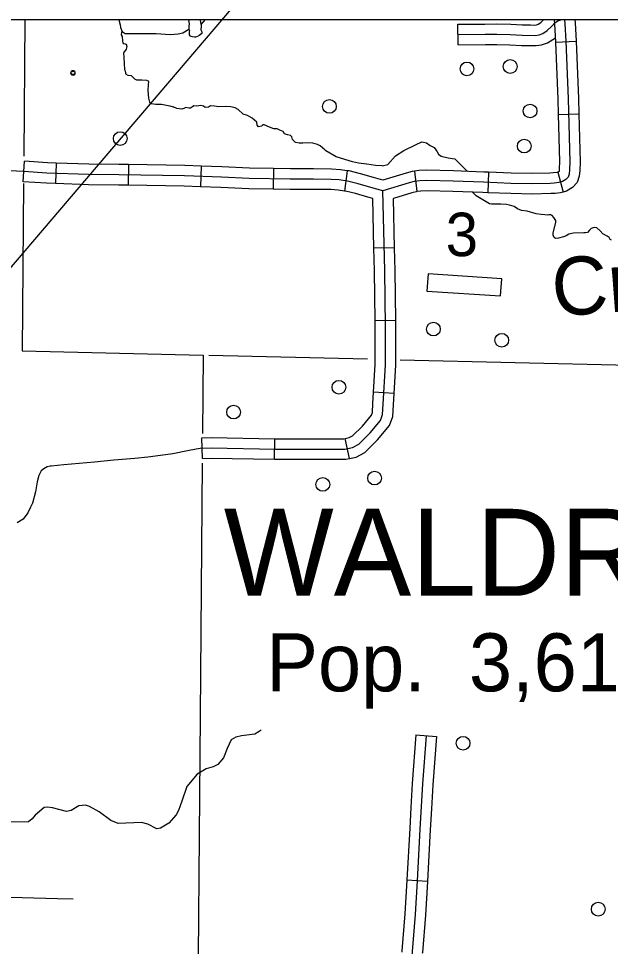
# Model space of a CAD drawing. Extents: x 1382482 to 1385815, y 1168351 to 1170484.
# Drawn here: x 1384491.5 to 1384663.8, y 1169309.6 to 1169580 of the extents above; entities that cross this region are included whole.
import ezdxf

# ---------------------------------------------------------------- set-up
doc = ezdxf.new("R2010")
doc.units = 0
for name, color, linetype in [('32', 7, 'Continuous'), ('35', 7, 'Continuous'), ('45', 7, 'Continuous'), ('5', 7, 'Continuous'), ('57', 7, 'Continuous'), ('6', 7, 'Continuous'), ('Default', 7, 'Continuous'), ('R_Dimension', 7, 'Continuous'), ('R_No Plot', 7, 'Continuous')]:
    doc.layers.add(name, color=color, linetype=linetype)

msp = doc.modelspace()

# ---------------------------------------------------------------- linework, layer by layer
at = {"layer": '32'}
for p, q in [((1384647.84, 1169573.11), (1384653.84, 1169573.35)), ((1384648.63, 1169552.04), (1384654.63, 1169552.21)), ((1384502.45, 1169537.87), (1384502.23, 1169531.87)), ((1384523.5, 1169537.4), (1384523.41, 1169531.4)), ((1384544.67, 1169536.98), (1384544.46, 1169530.98)), ((1384565.73, 1169536.27), (1384565.62, 1169530.27)), ((1384587.19, 1169535.63), (1384586.34, 1169529.69)), ((1384606.78, 1169535.5), (1384607.45, 1169529.54)), ((1384628.32, 1169535.19), (1384628.1, 1169529.2)), ((1384648.52, 1169535.22), (1384650.07, 1169529.42)), ((1384600.95, 1169513.17), (1384594.95, 1169513.04)), ((1384601.3, 1169492.03), (1384595.3, 1169491.94)), ((1384600.82, 1169470.7), (1384594.83, 1169471.07)), ((1384545.05, 1169451.79), (1384544.88, 1169457.79)), ((1384566.03, 1169451.56), (1384566.13, 1169457.56)), ((1384587.79, 1169451.76), (1384586.58, 1169457.63))]:
    msp.add_line(p, q, dxfattribs=at)
for points in [[(1384650.48, 1169579.7), (1384650.58, 1169578.46), (1384650.84, 1169573.36), (1384651.51, 1169556.59), (1384652.03, 1169538.25), (1384651.92, 1169535.94), (1384651.8, 1169534.67), (1384651.47, 1169533.74), (1384650.87, 1169533.07), (1384649.87, 1169532.47), (1384648.75, 1169532.17), (1384647.45, 1169532.02), (1384646.29, 1169531.95), (1384641.15, 1169531.8), (1384634.86, 1169531.95), (1384626.81, 1169532.25), (1384618.03, 1169532.62), (1384610.35, 1169532.81), (1384608.33, 1169532.66), (1384606.7, 1169532.47), (1384605.17, 1169532.06), (1384597.57, 1169529.79)], [(1384647.48, 1169579.7), (1384647.58, 1169578.28), (1384647.84, 1169573.22), (1384647.84, 1169573.11)], [(1384653.49, 1169579.7), (1384653.57, 1169578.65), (1384653.83, 1169573.49), (1384653.84, 1169573.35)], [(1384647.84, 1169573.11), (1384648.51, 1169556.48), (1384648.63, 1169552.04)], [(1384653.84, 1169573.35), (1384654.5, 1169556.69), (1384654.63, 1169552.21)], [(1384648.63, 1169552.04), (1384649.03, 1169538.28), (1384648.92, 1169536.14), (1384648.85, 1169535.36), (1384648.69, 1169535.26), (1384648.52, 1169535.22)], [(1384654.63, 1169552.21), (1384655.03, 1169538.22), (1384654.91, 1169535.73), (1384654.76, 1169534.02), (1384654.1, 1169532.18), (1384652.8, 1169530.73), (1384651.04, 1169529.68), (1384650.07, 1169529.42)], [(1384502.23, 1169531.87), (1384499.56, 1169531.97), (1384492.77, 1169532.42), (1384493.17, 1169538.41)], [(1384502.45, 1169537.87), (1384499.87, 1169537.96), (1384493.17, 1169538.41)], [(1384523.5, 1169537.4), (1384520.68, 1169537.44), (1384511.93, 1169537.52), (1384502.45, 1169537.87)], [(1384597.57, 1169529.79), (1384594.03, 1169530.77), (1384590.31, 1169531.85), (1384587.22, 1169532.6), (1384584.87, 1169532.93), (1384582.49, 1169533.12), (1384577.35, 1169533.16), (1384570.59, 1169533.18), (1384558.6, 1169533.4), (1384550.52, 1169533.77), (1384539.79, 1169534.15), (1384520.65, 1169534.44), (1384511.86, 1169534.52), (1384499.72, 1169534.96), (1384492.97, 1169535.41)], [(1384544.67, 1169536.98), (1384539.87, 1169537.14), (1384523.5, 1169537.4)], [(1384565.73, 1169536.27), (1384558.69, 1169536.4), (1384550.64, 1169536.77), (1384544.67, 1169536.98)], [(1384587.19, 1169535.63), (1384585.2, 1169535.92), (1384582.62, 1169536.12), (1384577.36, 1169536.16), (1384570.62, 1169536.18), (1384565.73, 1169536.27)], [(1384606.78, 1169535.5), (1384606.13, 1169535.43), (1384604.35, 1169534.95), (1384597.54, 1169532.91), (1384594.85, 1169533.66), (1384591.08, 1169534.75), (1384587.78, 1169535.55), (1384587.19, 1169535.63)], [(1384628.32, 1169535.19), (1384626.93, 1169535.25), (1384618.13, 1169535.62), (1384610.27, 1169535.81), (1384608.05, 1169535.65), (1384606.78, 1169535.5)], [(1384648.52, 1169535.22), (1384648.19, 1169535.13), (1384647.18, 1169535.01), (1384646.15, 1169534.95), (1384641.14, 1169534.8), (1384634.95, 1169534.95), (1384628.32, 1169535.19)], [(1384523.41, 1169531.4), (1384520.61, 1169531.44), (1384511.79, 1169531.52), (1384502.23, 1169531.87)], [(1384544.46, 1169530.98), (1384539.72, 1169531.15), (1384523.41, 1169531.4)], [(1384565.62, 1169530.27), (1384558.5, 1169530.4), (1384550.4, 1169530.78), (1384544.46, 1169530.98)], [(1384544.96, 1169454.79), (1384547.55, 1169454.87), (1384566.26, 1169454.55), (1384584.01, 1169454.55), (1384586.5, 1169454.55), (1384588.75, 1169455.02), (1384590.54, 1169455.95), (1384593.81, 1169459.22), (1384596.85, 1169462.88), (1384597.47, 1169464.6), (1384597.63, 1169467.63), (1384598.33, 1169479.08), (1384598.33, 1169490.17), (1384598.09, 1169506.52), (1384597.57, 1169529.79)], [(1384586.34, 1169529.69), (1384584.54, 1169529.95), (1384582.36, 1169530.12), (1384577.33, 1169530.16), (1384570.56, 1169530.18), (1384565.62, 1169530.27)], [(1384594.62, 1169527.5), (1384593.21, 1169527.89), (1384589.54, 1169528.95), (1384586.65, 1169529.65), (1384586.34, 1169529.69)], [(1384628.1, 1169529.2), (1384626.7, 1169529.25), (1384617.93, 1169529.62), (1384610.42, 1169529.8), (1384608.61, 1169529.67), (1384607.45, 1169529.54)], [(1384594.95, 1169513.04), (1384594.62, 1169527.5)], [(1384607.45, 1169529.54), (1384607.26, 1169529.52), (1384605.99, 1169529.18), (1384600.62, 1169527.57)], [(1384600.95, 1169513.17), (1384600.62, 1169527.57)], [(1384650.07, 1169529.42), (1384649.31, 1169529.22), (1384647.71, 1169529.04), (1384646.43, 1169528.95), (1384641.16, 1169528.8), (1384634.77, 1169528.95), (1384628.1, 1169529.2)], [(1384595.3, 1169491.94), (1384595.09, 1169506.47), (1384594.95, 1169513.04)], [(1384601.3, 1169492.03), (1384601.09, 1169506.58), (1384600.95, 1169513.17)], [(1384594.83, 1169471.07), (1384595.33, 1169479.17), (1384595.33, 1169490.15), (1384595.3, 1169491.94)], [(1384600.82, 1169470.7), (1384601.33, 1169478.99), (1384601.33, 1169490.19), (1384601.3, 1169492.03)], [(1384586.58, 1169457.63), (1384587.74, 1169457.87), (1384588.75, 1169458.4), (1384591.59, 1169461.25), (1384594.21, 1169464.4), (1384594.5, 1169465.2), (1384594.63, 1169467.8), (1384594.83, 1169471.07)], [(1384587.79, 1169451.76), (1384589.77, 1169452.17), (1384592.34, 1169453.51), (1384596.03, 1169457.2), (1384599.49, 1169461.37), (1384600.44, 1169463.99), (1384600.62, 1169467.46), (1384600.82, 1169470.7)], [(1384544.88, 1169457.79), (1384547.54, 1169457.87), (1384566.13, 1169457.56)], [(1384566.13, 1169457.56), (1384566.29, 1169457.55), (1384584.01, 1169457.55), (1384586.19, 1169457.55), (1384586.58, 1169457.63)], [(1384545.05, 1169451.79), (1384547.57, 1169451.86), (1384566.03, 1169451.56)], [(1384566.03, 1169451.56), (1384566.24, 1169451.55), (1384584.01, 1169451.55), (1384586.8, 1169451.55), (1384587.79, 1169451.76)]]:
    msp.add_lwpolyline(points, dxfattribs=at)
at = {"layer": '35'}
for points in [[(1384520.68, 1169579.7), (1384520.77, 1169579.22), (1384521.05, 1169578.09), (1384521.14, 1169577.38), (1384521.65, 1169576.22), (1384522.48, 1169575.64), (1384523.26, 1169575.57), (1384524.15, 1169575.57), (1384525.24, 1169575.57), (1384527.46, 1169575.61), (1384529.94, 1169575.57), (1384531.58, 1169575.57), (1384535.63, 1169575.33), (1384537.92, 1169575.48), (1384539.32, 1169575.84), (1384541.02, 1169576.88)], [(1384541.22, 1169579.7), (1384540.98, 1169579.14), (1384541, 1169578.97), (1384541.16, 1169578.5), (1384541.08, 1169577.68), (1384541.02, 1169576.88), (1384541.16, 1169576.67), (1384541.27, 1169576.53), (1384541.16, 1169576.07), (1384541.19, 1169575.23), (1384541.35, 1169574.92), (1384541.6, 1169574.84), (1384542.13, 1169574.72), (1384542.67, 1169574.68), (1384543.08, 1169574.68), (1384543.39, 1169574.76), (1384543.84, 1169574.96)], [(1384544.21, 1169579.7), (1384544.35, 1169579.48), (1384544.48, 1169578.83), (1384544.53, 1169578.31), (1384544.64, 1169578.2), (1384544.68, 1169577.79)], [(1384544.64, 1169578.2), (1384545.93, 1169579.7)], [(1384521.65, 1169576.22), (1384521.4, 1169576.02), (1384521.36, 1169575.24), (1384521.59, 1169574.69), (1384521.75, 1169573.37), (1384521.79, 1169572.94), (1384521.9, 1169572.71), (1384522.52, 1169572.59), (1384522.8, 1169572.51), (1384523.03, 1169571.85), (1384522.76, 1169571), (1384522.06, 1169569.98), (1384522.1, 1169568.62), (1384522.29, 1169565.16), (1384522.49, 1169564.77), (1384522.6, 1169564.07), (1384522.64, 1169563.83), (1384523.26, 1169563.48), (1384524.24, 1169563.41), (1384525.21, 1169562.43), (1384525.83, 1169562.12), (1384526.46, 1169562.08), (1384527.39, 1169562.12), (1384528.75, 1169562), (1384529.22, 1169561.85), (1384529.3, 1169561.54), (1384529.18, 1169560.72), (1384529.06, 1169559.05), (1384529.26, 1169556.75), (1384529.61, 1169555.58), (1384530.11, 1169555.19), (1384531.44, 1169555.04), (1384533.11, 1169555.04), (1384535.48, 1169554.57), (1384536.48, 1169554.24)], [(1384544.68, 1169577.79), (1384544.57, 1169576.69), (1384544.79, 1169576.14), (1384544.79, 1169575.95), (1384544.79, 1169575.62), (1384544.02, 1169575), (1384543.84, 1169574.96)], [(1384580.64, 1169541.67), (1384579.29, 1169542.89), (1384578.51, 1169543.28), (1384577.11, 1169543.67), (1384575.86, 1169543.75), (1384574.23, 1169543.67), (1384573.14, 1169543.67), (1384572.13, 1169543.9), (1384571.27, 1169544.76), (1384571.04, 1169545.46), (1384570.65, 1169545.85), (1384569.79, 1169546.08), (1384568.93, 1169546.39), (1384568.47, 1169547.09), (1384567.53, 1169547.41), (1384566.76, 1169547.8), (1384565.82, 1169547.8), (1384564.5, 1169548.34), (1384563.02, 1169548.96), (1384562.63, 1169548.96), (1384562.16, 1169548.65), (1384561.38, 1169548.42), (1384560.92, 1169548.89), (1384560.84, 1169549.82), (1384559.52, 1169550.91), (1384558.12, 1169551.69), (1384556.9, 1169552.14), (1384555.46, 1169553.42), (1384554.56, 1169553.93), (1384553.32, 1169554.24), (1384551.64, 1169554.32), (1384549.7, 1169554.24), (1384548.53, 1169554.47), (1384547.33, 1169554.51), (1384546.75, 1169554.12), (1384545.85, 1169554.08), (1384545.34, 1169554.47), (1384544.53, 1169554.59), (1384543.4, 1169554.47), (1384542.51, 1169554.51), (1384542.12, 1169554.2), (1384541.57, 1169553.81), (1384541.07, 1169553.81), (1384540.21, 1169554.08), (1384539.63, 1169553.73), (1384539.04, 1169553.58), (1384538.27, 1169553.65), (1384537.53, 1169553.77), (1384536.48, 1169554.24)], [(1384597.39, 1169537.02), (1384598.98, 1169537.42), (1384601.25, 1169539.94), (1384603.66, 1169541.53), (1384607.05, 1169543.21), (1384608.91, 1169544.03), (1384609.42, 1169543.95), (1384610.28, 1169543.75), (1384611.29, 1169542.94), (1384612.46, 1169542.35), (1384613, 1169541.69), (1384613.35, 1169541.11), (1384613.78, 1169540.41), (1384614.56, 1169539.86), (1384616.55, 1169539.36), (1384618.53, 1169539.09), (1384619.84, 1169537.71), (1384622.23, 1169535.44)], [(1384597.39, 1169537.02), (1384595.43, 1169537.15), (1384592.93, 1169537.52), (1384590.44, 1169537.81), (1384588.66, 1169538.21), (1384583.93, 1169539.65), (1384580.92, 1169541.46), (1384580.64, 1169541.67)], [(1384647.89, 1169520.62), (1384647.92, 1169521.13), (1384647.53, 1169521.67), (1384647.3, 1169522.03), (1384646.83, 1169522.63), (1384646.49, 1169522.74), (1384645.85, 1169522.74), (1384645.46, 1169522.68), (1384644.69, 1169522.74), (1384643.63, 1169522.86), (1384642.18, 1169523.09), (1384639.62, 1169523.88), (1384637.97, 1169524.05), (1384636.76, 1169524.56), (1384635.74, 1169525.2), (1384634.39, 1169525.55), (1384633.51, 1169525.83), (1384631.92, 1169525.86), (1384630.42, 1169525.93), (1384629.17, 1169525.89), (1384628.63, 1169526.02), (1384627.63, 1169526.56), (1384627.14, 1169526.86), (1384624.72, 1169528.36), (1384623.66, 1169529.38)], [(1384647.12, 1169517.48), (1384647.89, 1169520.62)], [(1384664.17, 1169515.41), (1384663.78, 1169515.62), (1384663.48, 1169516.14), (1384662.84, 1169516.61), (1384661.64, 1169517.21), (1384660.87, 1169518.11), (1384659.89, 1169518.96), (1384659.29, 1169519.09), (1384658.82, 1169519.01), (1384658.22, 1169518.79), (1384657.74, 1169518.28), (1384657.1, 1169517.68), (1384656.59, 1169517.55), (1384656.07, 1169517.55), (1384653.03, 1169517.42), (1384651.71, 1169517.16), (1384650.89, 1169516.65), (1384650.16, 1169516.35), (1384648.71, 1169516.01), (1384647.81, 1169515.92), (1384647.42, 1169516.18), (1384647.12, 1169516.82), (1384647.12, 1169517.46), (1384647.12, 1169517.48)], [(1384562.12, 1169372.68), (1384561.57, 1169372.26), (1384560.22, 1169371.5), (1384556.4, 1169370.99), (1384554.69, 1169370.58), (1384553.38, 1169369.81), (1384552.24, 1169367.32), (1384551.14, 1169364.63), (1384549.52, 1169362.66), (1384548.16, 1169361.93), (1384546.14, 1169361.36), (1384543.51, 1169359.86), (1384540.47, 1169356.2), (1384538.98, 1169351.99), (1384538, 1169349.19), (1384537.33, 1169347.98), (1384535.27, 1169345.57), (1384532.81, 1169344.07), (1384531.7, 1169343.91), (1384529.06, 1169345.29), (1384527.3, 1169345.72), (1384520.45, 1169345.43), (1384518.33, 1169346.29), (1384514.92, 1169348.87), (1384512.08, 1169350.45), (1384510.92, 1169350.8), (1384509.05, 1169350.58), (1384506.75, 1169349.25), (1384505.43, 1169348.96), (1384501.36, 1169350.01), (1384499.93, 1169350.2), (1384498.89, 1169350.07), (1384496.31, 1169347.9), (1384495.44, 1169346.85), (1384494.37, 1169345.96), (1384488.05, 1169345.82)]]:
    msp.add_lwpolyline(points, dxfattribs=at)
at = {"layer": '45'}
for p, q in [((1384619.47, 1169572.3), (1384619.42, 1169578.3)), ((1384607.15, 1169371.24), (1384613.13, 1169370.8)), ((1384604.53, 1169329.03), (1384610.52, 1169328.69))]:
    msp.add_line(p, q, dxfattribs=at)
for points in [[(1384619.42, 1169578.3), (1384627.29, 1169578.37), (1384630.75, 1169578.45), (1384634.78, 1169578.29), (1384638.16, 1169578.11), (1384640.58, 1169578.09)], [(1384619.44, 1169575.3), (1384627.34, 1169575.37), (1384630.73, 1169575.44), (1384634.64, 1169575.3), (1384638.07, 1169575.11), (1384641.98, 1169575.07), (1384643.02, 1169575.22), (1384644.14, 1169575.63), (1384645.44, 1169576.45), (1384646.71, 1169577.72), (1384647.7, 1169578.8), (1384648.48, 1169579.28), (1384649.12, 1169579.51), (1384649.79, 1169579.65)], [(1384640.58, 1169578.09), (1384641.78, 1169578.07), (1384642.28, 1169578.15), (1384642.81, 1169578.34), (1384643.56, 1169578.81), (1384644.44, 1169579.7)], [(1384640.53, 1169572.09), (1384642.18, 1169572.07), (1384643.76, 1169572.3), (1384645.47, 1169572.92), (1384647.78, 1169574.38)], [(1384619.47, 1169572.3), (1384627.39, 1169572.37), (1384630.71, 1169572.44), (1384634.5, 1169572.3), (1384637.97, 1169572.11), (1384640.53, 1169572.09)], [(1384610.14, 1169371.02), (1384609.13, 1169356.96), (1384608.36, 1169343.82), (1384607.52, 1169328.74), (1384606.92, 1169318.92), (1384606.08, 1169308.13), (1384605.63, 1169302.01), (1384605.42, 1169299.98), (1384605.17, 1169298.24), (1384604.62, 1169296.5), (1384603.9, 1169294.76), (1384603.43, 1169293.49), (1384602.88, 1169292.35), (1384602.75, 1169291.55), (1384603.13, 1169290.66), (1384603.51, 1169289.94), (1384603.86, 1169289.02)], [(1384607.15, 1169371.24), (1384606.13, 1169357.15), (1384605.72, 1169350.12)], [(1384613.13, 1169370.8), (1384612.12, 1169356.76), (1384611.71, 1169349.77)], [(1384605.72, 1169350.12), (1384605.37, 1169343.99), (1384604.53, 1169329.03)], [(1384611.71, 1169349.77), (1384611.36, 1169343.65), (1384610.52, 1169328.69)], [(1384604.53, 1169329.03), (1384604.52, 1169328.92), (1384603.93, 1169319.12), (1384603.09, 1169308.36), (1384603.06, 1169308.01)], [(1384610.52, 1169328.69), (1384610.51, 1169328.57), (1384609.92, 1169318.71), (1384609.07, 1169307.9), (1384609.04, 1169307.58)]]:
    msp.add_lwpolyline(points, dxfattribs=at)
at = {"layer": '5'}
for points in [[(1384493.32, 1169579.7), (1384493, 1169539.9)], [(1384546.86, 1169481.89), (1384593.12, 1169480.79)], [(1384602.62, 1169480.56), (1384703.1, 1169478.17)]]:
    msp.add_lwpolyline(points, dxfattribs=at)
at = {"layer": '57'}
for p, q in [((1384610.7, 1169505.57), (1384610.37, 1169500.58)), ((1384632.15, 1169504.15), (1384610.7, 1169505.57)), ((1384631.82, 1169499.16), (1384632.15, 1169504.15)), ((1384610.37, 1169500.58), (1384631.82, 1169499.16))]:
    msp.add_line(p, q, dxfattribs=at)
for centre in [(1384507.29, 1169564.25), (1384507.29, 1169563.99)]:
    msp.add_circle(centre, 0.6, dxfattribs=at)
at = {"layer": '6'}
for points in [[(1384492.94, 1169531.91), (1384492.55, 1169483.19), (1384545.19, 1169481.93), (1384545, 1169459.09)], [(1384544.93, 1169450.44), (1384544.32, 1169376.84), (1384543.45, 1169271.74), (1384551.85, 1169271.53)]]:
    msp.add_lwpolyline(points, dxfattribs=at)
at = {"layer": 'Default'}
for points in [[(1384492.97, 1169535.41), (1384477.77, 1169536.1), (1384464.06, 1169536.45), (1384456.59, 1169536.85), (1384452.77, 1169537.15), (1384450.84, 1169537.2), (1384448.8, 1169537.03), (1384445.01, 1169537.03), (1384442.27, 1169536.91), (1384439.87, 1169536.74), (1384437.77, 1169536.33), (1384435.67, 1169536.21), (1384432.76, 1169536.1), (1384427.97, 1169536.33), (1384416.09, 1169535.98), (1384409.67, 1169535.8), (1384401.51, 1169535.8), (1384392.07, 1169535.98), (1384389.77, 1169535.61)], [(1384544.96, 1169454.79), (1384543.19, 1169454.51), (1384540.7, 1169454.01), (1384536.42, 1169453.15), (1384532.76, 1169452.65), (1384529.07, 1169452.14), (1384525.29, 1169451.79), (1384519.18, 1169451.28), (1384513.6, 1169450.76), (1384504.69, 1169449.98), (1384500.95, 1169449.59), (1384500.64, 1169449.55), (1384499.82, 1169449.32), (1384498.85, 1169448.81), (1384498.03, 1169448.15), (1384497.37, 1169446.87), (1384496.91, 1169444.96), (1384496.36, 1169442.12), (1384495.5, 1169438.73), (1384494.97, 1169437.61), (1384494.12, 1169435.94), (1384492.8, 1169434.15), (1384491.08, 1169433.06)], [(1384483.05, 1169323.32), (1384484.24, 1169323.86), (1384485.35, 1169324.06), (1384487.73, 1169324.02), (1384492.54, 1169323.94), (1384502.85, 1169323.57), (1384507.32, 1169323.49)]]:
    msp.add_lwpolyline(points, dxfattribs=at)
for centre in [(1384634.63, 1169566), (1384622.05, 1169565.28), (1384581.98, 1169554.35), (1384640.4, 1169553.03), (1384521.08, 1169544.99), (1384638.73, 1169542.8), (1384612.28, 1169489.5), (1384632.17, 1169486.23), (1384584.74, 1169472.55), (1384554.07, 1169465.3), (1384580.06, 1169444.23), (1384595.14, 1169446.08), (1384620.89, 1169368.84), (1384660.29, 1169320.49)]:
    msp.add_circle(centre, 2, dxfattribs=at)
at = {"layer": 'R_Dimension'}
msp.add_line((1384666.56, 1169715.52), (1384203.4, 1169172.61), dxfattribs=at)
at = {"layer": 'R_No Plot'}
msp.add_lwpolyline([(1383432.46, 1169579.7), (1384939.88, 1169579.7), (1384939.88, 1168702.36), (1383432.46, 1168702.36)], close=True, dxfattribs=at)

# ---------------------------------------------------------------- texts
at = {"layer": '35'}
msp.add_text('Cr.', height=16.896, rotation=4.2959, dxfattribs=at).set_placement((1384647.34, 1169493.12))
at = {"layer": '57'}
msp.add_text('3', height=12.67, dxfattribs=at).set_placement((1384615.84, 1169510.74))
at = {"layer": '6'}
for s, height, p in [('WALDRON', 25.344, (1384551.24, 1169411.79)), ('Pop.  3,618', 16.896, (1384563.58, 1169383.96))]:
    msp.add_text(s, height=height, dxfattribs=at).set_placement(p)

doc.saveas('drawing.dxf')
